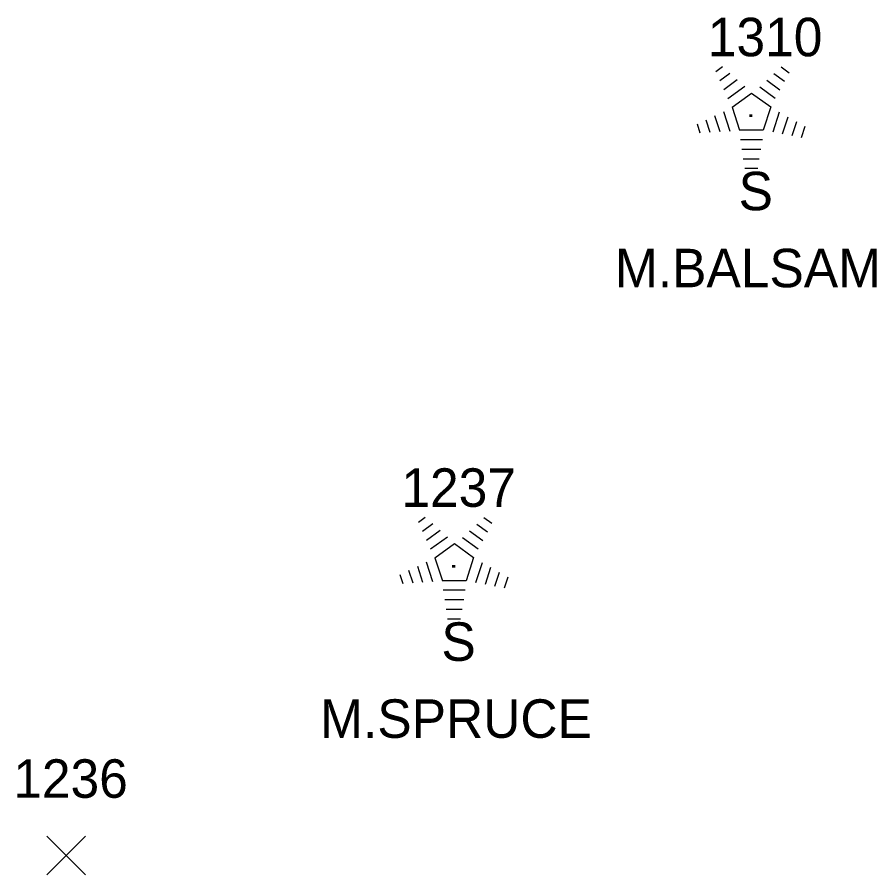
# Model space of a CAD drawing. Extents: x 1554917 to 1555870, y 813367 to 816333.
# Drawn here: x 1554993.91 to 1555038.56, y 813760.38 to 813804.93 of the extents above; entities that cross this region are included whole.
import ezdxf

# ---------------------------------------------------------------- set-up
doc = ezdxf.new("R2010")
doc.units = 0
for name, color, linetype in [('L_A', 7, 'Continuous'), ('L_C', 7, 'Continuous'), ('L_I', 7, 'Continuous'), ('L_TIC', 7, 'Continuous'), ('LTC', 7, 'Continuous')]:
    doc.layers.add(name, color=color, linetype=linetype)

msp = doc.modelspace()

# ---------------------------------------------------------------- linework, layer by layer
at = {"layer": 'L_TIC'}
for points in [[(1554995.458, 813760.377), (1554997.458, 813762.377)], [(1554997.458, 813760.377), (1554995.458, 813762.377)]]:
    msp.add_lwpolyline(points, dxfattribs=at)
at = {"layer": 'LTC'}
for p, q in [((1555030.191, 813802.105), (1555030.546, 813802.363)), ((1555033.59, 813802.346), (1555034.009, 813802.041)), ((1555030.401, 813801.64), (1555030.93, 813802.024)), ((1555030.61, 813801.174), (1555031.314, 813801.685)), ((1555032.847, 813801.649), (1555033.527, 813801.155)), ((1555033.218, 813801.997), (1555033.768, 813801.598)), ((1555030.82, 813800.708), (1555031.698, 813801.346)), ((1555032.476, 813801.301), (1555033.286, 813800.712)), ((1555031.045, 813800.253), (1555032.056, 813800.988)), ((1555032.056, 813800.988), (1555033.053, 813800.263)), ((1555031.045, 813800.253), (1555031.432, 813799.06)), ((1555033.053, 813800.263), (1555032.662, 813799.06)), ((1555030.135, 813799.818), (1555030.406, 813798.982)), ((1555030.59, 813800.034), (1555030.921, 813799.015)), ((1555033.491, 813799.992), (1555033.153, 813798.952)), ((1555029.224, 813799.385), (1555029.376, 813798.917)), ((1555029.679, 813799.601), (1555029.891, 813798.95)), ((1555033.935, 813799.742), (1555033.648, 813798.857)), ((1555034.38, 813799.492), (1555034.143, 813798.762)), ((1555032.662, 813799.06), (1555031.432, 813799.06)), ((1555034.824, 813799.241), (1555034.637, 813798.667)), ((1555032.624, 813798.56), (1555031.479, 813798.56)), ((1555032.54, 813798.06), (1555031.552, 813798.06)), ((1555032.456, 813797.56), (1555031.625, 813797.56)), ((1555032.372, 813797.06), (1555031.697, 813797.06)), ((1555014.756, 813778.7), (1555015.11, 813778.958)), ((1555018.154, 813778.941), (1555018.573, 813778.636)), ((1555014.965, 813778.235), (1555015.494, 813778.619)), ((1555017.783, 813778.593), (1555018.332, 813778.193)), ((1555015.175, 813777.769), (1555015.879, 813778.28)), ((1555015.384, 813777.303), (1555016.263, 813777.941)), ((1555017.412, 813778.244), (1555018.091, 813777.75)), ((1555015.609, 813776.848), (1555016.621, 813777.583)), ((1555016.621, 813777.583), (1555017.618, 813776.858)), ((1555017.041, 813777.896), (1555017.85, 813777.307)), ((1555015.154, 813776.629), (1555015.485, 813775.61)), ((1555015.609, 813776.848), (1555015.996, 813775.655)), ((1555017.618, 813776.858), (1555017.226, 813775.655)), ((1555018.055, 813776.587), (1555017.717, 813775.548)), ((1555014.244, 813776.196), (1555014.455, 813775.545)), ((1555014.699, 813776.413), (1555014.97, 813775.578)), ((1555018.5, 813776.337), (1555018.212, 813775.452)), ((1555013.788, 813775.98), (1555013.94, 813775.512)), ((1555018.944, 813776.087), (1555018.707, 813775.357)), ((1555019.389, 813775.836), (1555019.202, 813775.262)), ((1555017.226, 813775.655), (1555015.996, 813775.655)), ((1555017.188, 813775.155), (1555016.044, 813775.155)), ((1555017.104, 813774.655), (1555016.116, 813774.655)), ((1555017.021, 813774.155), (1555016.189, 813774.155)), ((1555016.937, 813773.655), (1555016.262, 813773.655))]:
    msp.add_line(p, q, dxfattribs=at)

# ---------------------------------------------------------------- texts
at = {"layer": 'L_A'}
for p in [(1555031.382, 813794.897), (1555015.946, 813771.492)]:
    msp.add_text('S', height=2, dxfattribs=at).set_placement(p)
at = {"layer": 'L_C'}
for s, p in [('M.BALSAM', (1555024.957, 813790.897)), ('M.SPRUCE', (1555009.647, 813767.492))]:
    msp.add_text(s, height=2, dxfattribs=at).set_placement(p)
at = {"layer": 'L_I'}
for s, p in [('1310', (1555029.783, 813802.897)), ('1237', (1555013.868, 813779.492)), ('1236', (1554993.71, 813764.377))]:
    msp.add_text(s, height=2, dxfattribs=at).set_placement(p)
at = {"layer": 'LTC'}
for p in [(1555031.939, 813800.001), (1555016.503, 813776.596)]:
    msp.add_text('.', height=1.037, rotation=270, dxfattribs=at).set_placement(p)

doc.saveas('drawing.dxf')
